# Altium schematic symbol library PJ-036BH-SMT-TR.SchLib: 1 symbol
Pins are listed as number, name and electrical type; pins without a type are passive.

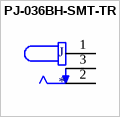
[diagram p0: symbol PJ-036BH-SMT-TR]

## PJ-036BH-SMT-TR
designator J
2.5 x 6.3 mm, 5.0 A, Horizontal, Surface Mount _SMT_, Dc Power Jack Connector; MP: PJ-036BH-SMT-TR; MF: CUI Devices
footprint CUI_PJ-036BH-SMT-TR
pins: 1, 2, 3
